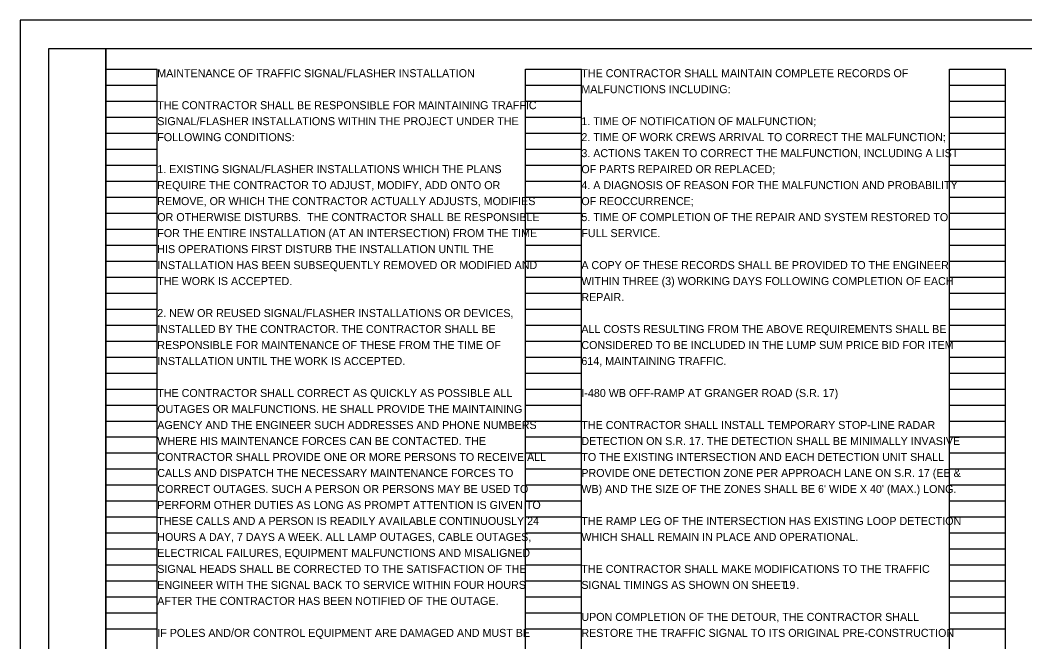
# Model space of a CAD drawing. Extents: x -18.6 to 78.7, y 0 to 36.9.
# Drawn here: x 0 to 17.58, y 11.11 to 22 of the extents above; entities that cross this region are included whole.
import ezdxf

# ---------------------------------------------------------------- set-up
doc = ezdxf.new("R2010")
doc.units = 0
for name, color, linetype in [('SH_Border', 7, 'Continuous'), ('SH_Cut_Line', 7, 'Continuous'), ('SH_Data', 7, 'Continuous'), ('SH_Text', 7, 'Continuous')]:
    doc.layers.add(name, color=color, linetype=linetype)

msp = doc.modelspace()

# ---------------------------------------------------------------- linework, layer by layer
at = {"layer": 'SH_Border'}
for points in [[(0.5, 21.5), (1.5, 21.5), (1.5, 0.5), (0.5, 0.5)], [(1.5, 21.5), (33.5, 21.5), (33.5, 0.5), (1.5, 0.5)]]:
    msp.add_lwpolyline(points, close=True, dxfattribs=at)
at = {"layer": 'SH_Cut_Line'}
msp.add_lwpolyline([(0, 0), (34, 0), (34, 22), (0, 22)], close=True, dxfattribs=at)
at = {"layer": 'SH_Data'}
for p, q in [((1.5, 0.98), (1.5, 21.14)), ((1.5, 21.14), (2.4, 21.14)), ((2.4, 0.98), (2.4, 21.14)), ((8.84, 0.98), (8.84, 21.14)), ((8.84, 21.14), (9.82, 21.14)), ((9.82, 0.98), (9.82, 21.14)), ((16.26, 0.98), (16.26, 21.14)), ((16.26, 21.14), (17.24, 21.14)), ((17.24, 0.98), (17.24, 21.14)), ((1.5, 20.86), (2.4, 20.86)), ((8.84, 20.86), (9.82, 20.86)), ((16.26, 20.86), (17.24, 20.86)), ((1.5, 20.58), (2.4, 20.58)), ((8.84, 20.58), (9.82, 20.58)), ((16.26, 20.58), (17.24, 20.58)), ((1.5, 20.3), (2.4, 20.3)), ((8.84, 20.3), (9.82, 20.3)), ((16.26, 20.3), (17.24, 20.3)), ((1.5, 20.02), (2.4, 20.02)), ((8.84, 20.02), (9.82, 20.02)), ((16.26, 20.02), (17.24, 20.02)), ((1.5, 19.74), (2.4, 19.74)), ((8.84, 19.74), (9.82, 19.74)), ((16.26, 19.74), (17.24, 19.74)), ((1.5, 19.46), (2.4, 19.46)), ((8.84, 19.46), (9.82, 19.46)), ((16.26, 19.46), (17.24, 19.46)), ((1.5, 19.18), (2.4, 19.18)), ((8.84, 19.18), (9.82, 19.18)), ((16.26, 19.18), (17.24, 19.18)), ((1.5, 18.9), (2.4, 18.9)), ((8.84, 18.9), (9.82, 18.9)), ((16.26, 18.9), (17.24, 18.9)), ((1.5, 18.62), (2.4, 18.62)), ((8.84, 18.62), (9.82, 18.62)), ((16.26, 18.62), (17.24, 18.62)), ((1.5, 18.34), (2.4, 18.34)), ((8.84, 18.34), (9.82, 18.34)), ((16.26, 18.34), (17.24, 18.34)), ((1.5, 18.06), (2.4, 18.06)), ((8.84, 18.06), (9.82, 18.06)), ((16.26, 18.06), (17.24, 18.06)), ((1.5, 17.78), (2.4, 17.78)), ((8.84, 17.78), (9.82, 17.78)), ((16.26, 17.78), (17.24, 17.78)), ((1.5, 17.5), (2.4, 17.5)), ((8.84, 17.5), (9.82, 17.5)), ((16.26, 17.5), (17.24, 17.5)), ((1.5, 17.22), (2.4, 17.22)), ((8.84, 17.22), (9.82, 17.22)), ((16.26, 17.22), (17.24, 17.22)), ((1.5, 16.94), (2.4, 16.94)), ((8.84, 16.94), (9.82, 16.94)), ((16.26, 16.94), (17.24, 16.94)), ((1.5, 16.66), (2.4, 16.66)), ((8.84, 16.66), (9.82, 16.66)), ((16.26, 16.66), (17.24, 16.66)), ((1.5, 16.38), (2.4, 16.38)), ((8.84, 16.38), (9.82, 16.38)), ((16.26, 16.38), (17.24, 16.38)), ((1.5, 16.1), (2.4, 16.1)), ((8.84, 16.1), (9.82, 16.1)), ((16.26, 16.1), (17.24, 16.1)), ((1.5, 15.82), (2.4, 15.82)), ((8.84, 15.82), (9.82, 15.82)), ((16.26, 15.82), (17.24, 15.82)), ((1.5, 15.54), (2.4, 15.54)), ((8.84, 15.54), (9.82, 15.54)), ((16.26, 15.54), (17.24, 15.54)), ((1.5, 15.26), (2.4, 15.26)), ((8.84, 15.26), (9.82, 15.26)), ((16.26, 15.26), (17.24, 15.26)), ((1.5, 14.98), (2.4, 14.98)), ((8.84, 14.98), (9.82, 14.98)), ((16.26, 14.98), (17.24, 14.98)), ((1.5, 14.7), (2.4, 14.7)), ((8.84, 14.7), (9.82, 14.7)), ((16.26, 14.7), (17.24, 14.7)), ((1.5, 14.42), (2.4, 14.42)), ((8.84, 14.42), (9.82, 14.42)), ((16.26, 14.42), (17.24, 14.42)), ((1.5, 14.14), (2.4, 14.14)), ((8.84, 14.14), (9.82, 14.14)), ((16.26, 14.14), (17.24, 14.14)), ((1.5, 13.86), (2.4, 13.86)), ((8.84, 13.86), (9.82, 13.86)), ((16.26, 13.86), (17.24, 13.86)), ((1.5, 13.58), (2.4, 13.58)), ((8.84, 13.58), (9.82, 13.58)), ((16.26, 13.58), (17.24, 13.58)), ((1.5, 13.3), (2.4, 13.3)), ((8.84, 13.3), (9.82, 13.3)), ((16.26, 13.3), (17.24, 13.3)), ((1.5, 13.02), (2.4, 13.02)), ((8.84, 13.02), (9.82, 13.02)), ((16.26, 13.02), (17.24, 13.02)), ((1.5, 12.74), (2.4, 12.74)), ((8.84, 12.74), (9.82, 12.74)), ((16.26, 12.74), (17.24, 12.74)), ((1.5, 12.46), (2.4, 12.46)), ((8.84, 12.46), (9.82, 12.46)), ((16.26, 12.46), (17.24, 12.46)), ((1.5, 12.18), (2.4, 12.18)), ((8.84, 12.18), (9.82, 12.18)), ((16.26, 12.18), (17.24, 12.18)), ((1.5, 11.9), (2.4, 11.9)), ((8.84, 11.9), (9.82, 11.9)), ((16.26, 11.9), (17.24, 11.9)), ((1.5, 11.62), (2.4, 11.62)), ((8.84, 11.62), (9.82, 11.62)), ((16.26, 11.62), (17.24, 11.62)), ((1.5, 11.34), (2.4, 11.34)), ((8.84, 11.34), (9.82, 11.34)), ((16.26, 11.34), (17.24, 11.34))]:
    msp.add_line(p, q, dxfattribs=at)

# ---------------------------------------------------------------- texts
at = {"layer": 'SH_Text'}
for s, p in [('MAINTENANCE OF TRAFFIC SIGNAL/FLASHER INSTALLATION', (2.4, 21)), ('THE CONTRACTOR SHALL MAINTAIN COMPLETE RECORDS OF ', (9.82, 21)), ('MALFUNCTIONS INCLUDING:', (9.82, 20.72)), ('THE CONTRACTOR SHALL BE RESPONSIBLE FOR MAINTAINING TRAFFIC ', (2.4, 20.44)), ('SIGNAL/FLASHER INSTALLATIONS WITHIN THE PROJECT UNDER THE ', (2.4, 20.16)), ('1. TIME OF NOTIFICATION OF MALFUNCTION;', (9.82, 20.16)), ('FOLLOWING CONDITIONS:', (2.4, 19.88)), ('2. TIME OF WORK CREWS ARRIVAL TO CORRECT THE MALFUNCTION;', (9.82, 19.88)), ('3. ACTIONS TAKEN TO CORRECT THE MALFUNCTION, INCLUDING A LIST ', (9.82, 19.6)), ('1. EXISTING SIGNAL/FLASHER INSTALLATIONS WHICH THE PLANS ', (2.4, 19.32)), ('OF PARTS REPAIRED OR REPLACED;', (9.82, 19.32)), ('REQUIRE THE CONTRACTOR TO ADJUST, MODIFY, ADD ONTO OR ', (2.4, 19.04)), ('4. A DIAGNOSIS OF REASON FOR THE MALFUNCTION AND PROBABILITY ', (9.82, 19.04)), ('REMOVE, OR WHICH THE CONTRACTOR ACTUALLY ADJUSTS, MODIFIES ', (2.4, 18.76)), ('OF REOCCURRENCE;', (9.82, 18.76)), ('OR OTHERWISE DISTURBS.  THE CONTRACTOR SHALL BE RESPONSIBLE ', (2.4, 18.48)), ('5. TIME OF COMPLETION OF THE REPAIR AND SYSTEM RESTORED TO ', (9.82, 18.48)), ('FOR THE ENTIRE INSTALLATION (AT AN INTERSECTION) FROM THE TIME ', (2.4, 18.2)), ('FULL SERVICE.', (9.82, 18.2)), ('HIS OPERATIONS FIRST DISTURB THE INSTALLATION UNTIL THE ', (2.4, 17.92)), ('INSTALLATION HAS BEEN SUBSEQUENTLY REMOVED OR MODIFIED AND ', (2.4, 17.64)), ('A COPY OF THESE RECORDS SHALL BE PROVIDED TO THE ENGINEER ', (9.82, 17.64)), ('THE WORK IS ACCEPTED.', (2.4, 17.36)), ('WITHIN THREE (3) WORKING DAYS FOLLOWING COMPLETION OF EACH ', (9.82, 17.36)), ('REPAIR.', (9.82, 17.08)), ('2. NEW OR REUSED SIGNAL/FLASHER INSTALLATIONS OR DEVICES, ', (2.4, 16.8)), ('INSTALLED BY THE CONTRACTOR. THE CONTRACTOR SHALL BE ', (2.4, 16.52)), ('ALL COSTS RESULTING FROM THE ABOVE REQUIREMENTS SHALL BE ', (9.82, 16.52)), ('RESPONSIBLE FOR MAINTENANCE OF THESE FROM THE TIME OF ', (2.4, 16.24)), ('CONSIDERED TO BE INCLUDED IN THE LUMP SUM PRICE BID FOR ITEM ', (9.82, 16.24)), ('INSTALLATION UNTIL THE WORK IS ACCEPTED.', (2.4, 15.96)), ('614, MAINTAINING TRAFFIC.', (9.82, 15.96)), ('THE CONTRACTOR SHALL CORRECT AS QUICKLY AS POSSIBLE ALL ', (2.4, 15.4)), ('I-480 WB OFF-RAMP AT GRANGER ROAD (S.R. 17)', (9.82, 15.4)), ('OUTAGES OR MALFUNCTIONS. HE SHALL PROVIDE THE MAINTAINING ', (2.4, 15.12)), ('AGENCY AND THE ENGINEER SUCH ADDRESSES AND PHONE NUMBERS ', (2.4, 14.84)), ('THE CONTRACTOR SHALL INSTALL TEMPORARY STOP-LINE RADAR ', (9.82, 14.84)), ('WHERE HIS MAINTENANCE FORCES CAN BE CONTACTED. THE ', (2.4, 14.56)), ('DETECTION ON S.R. 17. THE DETECTION SHALL BE MINIMALLY INVASIVE ', (9.82, 14.56)), ('CONTRACTOR SHALL PROVIDE ONE OR MORE PERSONS TO RECEIVE ALL ', (2.4, 14.28)), ('TO THE EXISTING INTERSECTION AND EACH DETECTION UNIT SHALL ', (9.82, 14.28)), ('CALLS AND DISPATCH THE NECESSARY MAINTENANCE FORCES TO ', (2.4, 14)), ('PROVIDE ONE DETECTION ZONE PER APPROACH LANE ON S.R. 17 (EB & ', (9.82, 14)), ('CORRECT OUTAGES. SUCH A PERSON OR PERSONS MAY BE USED TO ', (2.4, 13.72)), ("WB) AND THE SIZE OF THE ZONES SHALL BE 6' WIDE X 40' (MAX.) LONG.", (9.82, 13.72)), ('PERFORM OTHER DUTIES AS LONG AS PROMPT ATTENTION IS GIVEN TO ', (2.4, 13.44)), ('THESE CALLS AND A PERSON IS READILY AVAILABLE CONTINUOUSLY 24 ', (2.4, 13.16)), ('THE RAMP LEG OF THE INTERSECTION HAS EXISTING LOOP DETECTION ', (9.82, 13.16)), ('HOURS A DAY, 7 DAYS A WEEK. ALL LAMP OUTAGES, CABLE OUTAGES, ', (2.4, 12.88)), ('WHICH SHALL REMAIN IN PLACE AND OPERATIONAL.', (9.82, 12.88)), ('ELECTRICAL FAILURES, EQUIPMENT MALFUNCTIONS AND MISALIGNED ', (2.4, 12.6)), ('SIGNAL HEADS SHALL BE CORRECTED TO THE SATISFACTION OF THE ', (2.4, 12.32)), ('THE CONTRACTOR SHALL MAKE MODIFICATIONS TO THE TRAFFIC ', (9.82, 12.32)), ('ENGINEER WITH THE SIGNAL BACK TO SERVICE WITHIN FOUR HOURS ', (2.4, 12.04)), ('SIGNAL TIMINGS AS SHOWN ON SHEET ', (9.82, 12.04)), ('19', (13.356, 12.04)), ('.', (13.58, 12.04)), ('AFTER THE CONTRACTOR HAS BEEN NOTIFIED OF THE OUTAGE.', (2.4, 11.76)), ('UPON COMPLETION OF THE DETOUR, THE CONTRACTOR SHALL ', (9.82, 11.48)), ('IF POLES AND/OR CONTROL EQUIPMENT ARE DAMAGED AND MUST BE ', (2.4, 11.2)), ('RESTORE THE TRAFFIC SIGNAL TO ITS ORIGINAL PRE-CONSTRUCTION ', (9.82, 11.2))]:
    msp.add_text(s, height=0.14, dxfattribs=at).set_placement(p)

doc.saveas('drawing.dxf')
